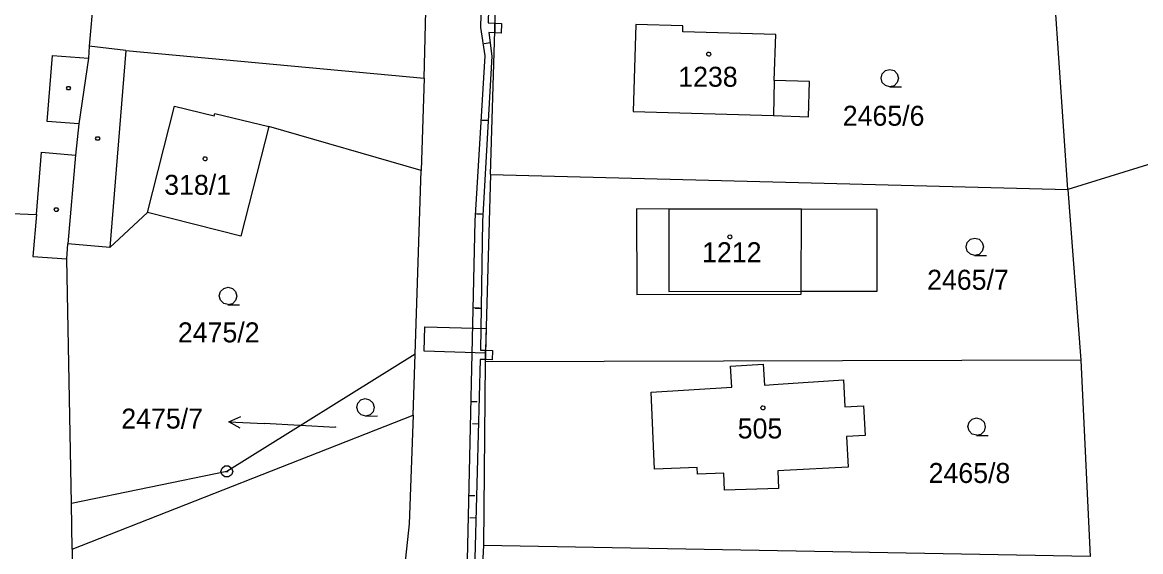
# Model space of a CAD drawing. Extents: x -760611 to -758411, y -1176479 to -1174807.
# Drawn here: x -759156.8 to -759061.6, y -1175074.4 to -1175029.4 of the extents above; entities that cross this region are included whole.
import ezdxf

# ---------------------------------------------------------------- set-up
doc = ezdxf.new("R2010")
doc.units = 0
for name, color, linetype in [('1', 7, 'Continuous'), ('12', 7, 'Continuous'), ('13', 7, 'Continuous'), ('2', 7, 'Continuous'), ('3', 7, 'Continuous'), ('4', 7, 'Continuous'), ('5', 7, 'Continuous'), ('7', 7, 'Continuous'), ('8', 7, 'Continuous')]:
    doc.layers.add(name, color=color, linetype=linetype)

msp = doc.modelspace()

# ---------------------------------------------------------------- linework, layer by layer
at = {"layer": '1'}
for p, q in [((-759122.62, -1175034.09), (-759121.67, -1174994.74)), ((-759149.99, -1175018.59), (-759151.16, -1175031.39)), ((-759116.98, -1175042.31), (-759116.51, -1175026.13)), ((-759067.85, -1175043.58), (-759068.96, -1175027.38)), ((-759104.61, -1175029.53), (-759104.84, -1175036.94)), ((-759100.62, -1175029.65), (-759104.61, -1175029.53)), ((-759100.63, -1175030.15), (-759100.62, -1175029.65)), ((-759092.71, -1175030.39), (-759100.63, -1175030.15)), ((-759092.83, -1175034.29), (-759092.71, -1175030.39)), ((-759025.28, -1175030.41), (-759067.85, -1175043.58)), ((-759151.16, -1175031.39), (-759151.2, -1175032.41)), ((-759148.04, -1175031.75), (-759151.16, -1175031.39)), ((-759151.2, -1175032.41), (-759152.02, -1175037.99)), ((-759148.04, -1175031.75), (-759122.62, -1175034.09)), ((-759122.62, -1175034.09), (-759122.89, -1175041.97)), ((-759089.83, -1175034.38), (-759092.83, -1175034.29)), ((-759089.92, -1175037.38), (-759089.83, -1175034.38)), ((-759104.84, -1175036.94), (-759092.91, -1175037.29)), ((-759152.02, -1175037.99), (-759152.32, -1175040.65)), ((-759092.91, -1175037.29), (-759089.92, -1175037.38)), ((-759135.85, -1175038.22), (-759138.23, -1175047.56)), ((-759122.89, -1175041.97), (-759135.85, -1175038.22)), ((-759152.32, -1175040.65), (-759152.96, -1175048.19)), ((-759123.41, -1175057.6), (-759122.89, -1175041.97)), ((-759116.98, -1175042.31), (-759117.43, -1175058.24)), ((-759116.98, -1175042.31), (-759067.85, -1175043.58)), ((-759067.85, -1175043.58), (-759066.75, -1175058.1)), ((-759158.43, -1175045.59), (-759155.64, -1175045.71)), ((-759155.64, -1175045.71), (-759155.93, -1175049.29)), ((-759146.17, -1175045.54), (-759149.39, -1175048.52)), ((-759138.23, -1175047.56), (-759146.17, -1175045.54)), ((-759101.8, -1175045.24), (-759104.56, -1175045.23)), ((-759104.56, -1175045.23), (-759104.54, -1175052.51)), ((-759090.51, -1175045.26), (-759101.8, -1175045.24)), ((-759084.08, -1175045.27), (-759090.51, -1175045.26)), ((-759084.08, -1175052.24), (-759084.08, -1175045.27)), ((-759153.04, -1175049.47), (-759152.96, -1175048.19)), ((-759149.39, -1175048.52), (-759152.96, -1175048.19)), ((-759155.93, -1175049.29), (-759153.04, -1175049.47)), ((-759152.66, -1175070.32), (-759153.04, -1175049.47)), ((-759090.53, -1175052.49), (-759090.53, -1175052.24)), ((-759090.53, -1175052.24), (-759084.08, -1175052.24)), ((-759104.54, -1175052.51), (-759090.53, -1175052.49)), ((-759123.41, -1175057.6), (-759139.43, -1175067.59)), ((-759123.58, -1175062.8), (-759123.41, -1175057.6)), ((-759066.75, -1175058.1), (-759117.43, -1175058.24)), ((-759066.75, -1175058.1), (-759065.95, -1175074.83)), ((-759117.43, -1175058.24), (-759117.58, -1175073.88)), ((-759096.56, -1175058.61), (-759093.77, -1175058.44)), ((-759096.45, -1175060.41), (-759096.56, -1175058.61)), ((-759093.77, -1175058.44), (-759093.66, -1175060.23)), ((-759092.51, -1175060.16), (-759086.95, -1175059.79)), ((-759086.95, -1175059.79), (-759086.82, -1175062.08)), ((-759103.32, -1175060.84), (-759096.45, -1175060.41)), ((-759103.03, -1175067.39), (-759103.32, -1175060.84)), ((-759093.66, -1175060.23), (-759092.51, -1175060.16)), ((-759152.59, -1175074.2), (-759123.58, -1175062.8)), ((-759123.58, -1175062.8), (-759123.9, -1175072.03)), ((-759086.82, -1175062.08), (-759085.24, -1175061.99)), ((-759085.24, -1175061.99), (-759085.11, -1175064.52)), ((-759085.11, -1175064.52), (-759086.68, -1175064.59)), ((-759086.68, -1175064.59), (-759086.55, -1175067.22)), ((-759139.43, -1175067.59), (-759152.66, -1175070.32)), ((-759099.4, -1175067.24), (-759103.03, -1175067.39)), ((-759099.38, -1175067.81), (-759099.4, -1175067.24)), ((-759092.03, -1175067.51), (-759092.52, -1175067.53)), ((-759092.52, -1175067.53), (-759092.46, -1175069.04)), ((-759086.55, -1175067.22), (-759092.03, -1175067.51)), ((-759097.14, -1175067.72), (-759099.38, -1175067.81)), ((-759097.08, -1175069.18), (-759097.14, -1175067.72)), ((-759092.46, -1175069.04), (-759097.08, -1175069.18)), ((-759152.59, -1175074.2), (-759152.66, -1175070.32)), ((-759123.9, -1175072.03), (-759125.97, -1175090.74)), ((-759152.59, -1175074.2), (-759152.74, -1175108.44)), ((-759117.58, -1175073.88), (-759118.32, -1175086.48)), ((-759065.95, -1175074.83), (-759117.58, -1175073.88))]:
    msp.add_line(p, q, dxfattribs=at)
at = {"layer": '12'}
for p, q in [((-759104.61, -1175029.53), (-759104.84, -1175036.94)), ((-759100.62, -1175029.65), (-759104.61, -1175029.53)), ((-759100.63, -1175030.15), (-759100.62, -1175029.65)), ((-759092.71, -1175030.39), (-759100.63, -1175030.15)), ((-759092.83, -1175034.29), (-759092.71, -1175030.39)), ((-759092.83, -1175034.29), (-759092.91, -1175037.29)), ((-759146.17, -1175045.54), (-759143.89, -1175036.48)), ((-759143.89, -1175036.48), (-759140.5, -1175037.3)), ((-759140.5, -1175037.3), (-759140.44, -1175037.11)), ((-759140.44, -1175037.11), (-759135.85, -1175038.22)), ((-759104.84, -1175036.94), (-759092.91, -1175037.29)), ((-759135.85, -1175038.22), (-759138.23, -1175047.56)), ((-759138.23, -1175047.56), (-759146.17, -1175045.54)), ((-759101.8, -1175045.24), (-759101.81, -1175052.26)), ((-759090.51, -1175045.26), (-759101.8, -1175045.24)), ((-759090.53, -1175052.24), (-759090.51, -1175045.26)), ((-759101.81, -1175052.26), (-759090.53, -1175052.24)), ((-759096.56, -1175058.61), (-759093.77, -1175058.44)), ((-759096.45, -1175060.41), (-759096.56, -1175058.61)), ((-759093.77, -1175058.44), (-759093.66, -1175060.23)), ((-759092.51, -1175060.16), (-759086.95, -1175059.79)), ((-759086.95, -1175059.79), (-759086.82, -1175062.08)), ((-759103.32, -1175060.84), (-759096.45, -1175060.41)), ((-759103.03, -1175067.39), (-759103.32, -1175060.84)), ((-759093.66, -1175060.23), (-759092.51, -1175060.16)), ((-759086.82, -1175062.08), (-759085.24, -1175061.99)), ((-759085.24, -1175061.99), (-759085.11, -1175064.52)), ((-759085.11, -1175064.52), (-759086.68, -1175064.59)), ((-759086.68, -1175064.59), (-759086.55, -1175067.22)), ((-759099.4, -1175067.24), (-759103.03, -1175067.39)), ((-759099.38, -1175067.81), (-759099.4, -1175067.24)), ((-759092.03, -1175067.51), (-759092.52, -1175067.53)), ((-759092.52, -1175067.53), (-759092.46, -1175069.04)), ((-759086.55, -1175067.22), (-759092.03, -1175067.51)), ((-759097.14, -1175067.72), (-759099.38, -1175067.81)), ((-759097.08, -1175069.18), (-759097.14, -1175067.72)), ((-759092.46, -1175069.04), (-759097.08, -1175069.18))]:
    msp.add_line(p, q, dxfattribs=at)
at = {"layer": '13'}
for p, q in [((-759117.02, -1175031.104), (-759117.516, -1175031.17)), ((-759117.771, -1175037.643), (-759117.272, -1175037.672)), ((-759117.187, -1175037.731), (-759117.686, -1175037.702)), ((-759118.243, -1175045.629), (-759117.744, -1175045.658)), ((-759117.648, -1175045.718), (-759118.147, -1175045.689)), ((-759118.449, -1175053.626), (-759117.949, -1175053.637)), ((-759117.795, -1175053.716), (-759118.295, -1175053.708)), ((-759122.63, -1175057.35), (-759122.57, -1175055.26)), ((-759122.57, -1175055.26), (-759117.35, -1175055.41)), ((-759117.35, -1175055.41), (-759117.41, -1175057.5)), ((-759117.41, -1175057.5), (-759122.63, -1175057.35)), ((-759118.631, -1175061.624), (-759118.132, -1175061.635)), ((-759118.02, -1175063.548), (-759118.52, -1175063.534)), ((-759118.814, -1175069.621), (-759118.314, -1175069.633)), ((-759118.238, -1175071.545), (-759118.738, -1175071.531))]:
    msp.add_line(p, q, dxfattribs=at)
for points in [[(-759117.8, -1175029.8), (-759117.31, -1175010.26), (-759116.14, -1174991.67), (-759120.15, -1174990.8), (-759120.24, -1174991.77), (-759121.26, -1174991.7), (-759121.06, -1174989.59)], [(-759116.72, -1175010.71), (-759117.19, -1175029.4), (-759116.61, -1175029.43), (-759116.63, -1175030.23), (-759117.14, -1175030.2), (-759116.87, -1175032.24)], [(-759118.94, -1175075.12), (-759118.28, -1175046.25), (-759117.45, -1175032.21), (-759117.8, -1175029.8)], [(-759116.87, -1175032.24), (-759117.68, -1175046.27), (-759117.85, -1175057.25), (-759117.4, -1175057.26), (-759117.42, -1175058.06), (-759117.87, -1175058.05)], [(-759117.87, -1175058.05), (-759118.39, -1175077.12), (-759117.86, -1175077.16), (-759117.9, -1175077.96), (-759118.45, -1175077.92), (-759119.04, -1175094.45), (-759118.58, -1175094.46), (-759118.6, -1175095.26)]]:
    msp.add_lwpolyline(points, dxfattribs=at)
for points in [[(-759116.05, -1175029.46), (-759116.09, -1175030.26), (-759116.63, -1175030.23), (-759116.61, -1175029.43)], [(-759116.82, -1175057.27), (-759116.84, -1175058.07), (-759117.42, -1175058.06), (-759117.4, -1175057.26)]]:
    msp.add_lwpolyline(points, close=True, dxfattribs=at)
at = {"layer": '3'}
for points in [[(-759082.99, -1175034.83), (-759083.37, -1175034.73), (-759083.64, -1175034.46), (-759083.74, -1175034.09), (-759083.64, -1175033.72), (-759083.37, -1175033.45), (-759083, -1175033.35), (-759082.63, -1175033.45), (-759082.36, -1175033.72), (-759082.26, -1175034.1), (-759082.36, -1175034.48), (-759082.63, -1175034.75), (-759083.01, -1175034.85), (-759082.01, -1175034.85)], [(-759075.76, -1175049.19), (-759076.14, -1175049.09), (-759076.41, -1175048.82), (-759076.51, -1175048.45), (-759076.41, -1175048.08), (-759076.14, -1175047.81), (-759075.77, -1175047.71), (-759075.4, -1175047.81), (-759075.13, -1175048.08), (-759075.03, -1175048.46), (-759075.13, -1175048.84), (-759075.4, -1175049.11), (-759075.78, -1175049.21), (-759074.78, -1175049.21)], [(-759139.32, -1175053.38), (-759139.7, -1175053.28), (-759139.97, -1175053.01), (-759140.07, -1175052.64), (-759139.97, -1175052.27), (-759139.7, -1175052), (-759139.33, -1175051.9), (-759138.96, -1175052), (-759138.69, -1175052.27), (-759138.59, -1175052.65), (-759138.69, -1175053.03), (-759138.96, -1175053.3), (-759139.34, -1175053.4), (-759138.34, -1175053.4)], [(-759127.6, -1175062.86), (-759127.983, -1175062.772), (-759128.261, -1175062.51), (-759128.373, -1175062.144), (-759128.284, -1175061.771), (-759128.023, -1175061.492), (-759127.656, -1175061.381), (-759127.283, -1175061.47), (-759127.005, -1175061.731), (-759126.893, -1175062.108), (-759126.981, -1175062.491), (-759127.243, -1175062.769), (-759127.619, -1175062.881), (-759126.62, -1175062.85)], [(-759075.6, -1175064.5), (-759075.98, -1175064.4), (-759076.25, -1175064.13), (-759076.35, -1175063.76), (-759076.25, -1175063.39), (-759075.98, -1175063.12), (-759075.61, -1175063.02), (-759075.24, -1175063.12), (-759074.97, -1175063.39), (-759074.87, -1175063.77), (-759074.97, -1175064.15), (-759075.24, -1175064.42), (-759075.62, -1175064.52), (-759074.62, -1175064.52)]]:
    msp.add_lwpolyline(points, dxfattribs=at)
at = {"layer": '4'}
for p, q in [((-759154.71, -1175037.78), (-759154.26, -1175032.17)), ((-759154.26, -1175032.17), (-759151.2, -1175032.41)), ((-759148.04, -1175031.75), (-759149.39, -1175048.52)), ((-759092.83, -1175034.29), (-759092.91, -1175037.29)), ((-759146.17, -1175045.54), (-759143.89, -1175036.48)), ((-759143.89, -1175036.48), (-759140.5, -1175037.3)), ((-759140.5, -1175037.3), (-759140.44, -1175037.11)), ((-759140.44, -1175037.11), (-759135.85, -1175038.22)), ((-759152.02, -1175037.99), (-759154.71, -1175037.78)), ((-759155.64, -1175045.71), (-759155.21, -1175040.41)), ((-759155.21, -1175040.41), (-759152.32, -1175040.65)), ((-759101.8, -1175045.24), (-759101.81, -1175052.26)), ((-759090.53, -1175052.24), (-759090.51, -1175045.26)), ((-759101.81, -1175052.26), (-759090.53, -1175052.24))]:
    msp.add_line(p, q, dxfattribs=at)
at = {"layer": '5'}
for points in [[(-759098.41, -1175031.89), (-759098.31, -1175031.91), (-759098.26, -1175032), (-759098.24, -1175032.06), (-759098.26, -1175032.15), (-759098.34, -1175032.22), (-759098.41, -1175032.23), (-759098.5, -1175032.2), (-759098.56, -1175032.14), (-759098.58, -1175032.06), (-759098.56, -1175031.97), (-759098.48, -1175031.9)], [(-759152.82, -1175034.8), (-759152.73, -1175034.95), (-759152.82, -1175035.1), (-759153, -1175035.1), (-759153.09, -1175034.95), (-759153, -1175034.8)], [(-759150.34, -1175039.09), (-759150.25, -1175039.24), (-759150.34, -1175039.39), (-759150.52, -1175039.39), (-759150.61, -1175039.24), (-759150.52, -1175039.09)], [(-759141.28, -1175040.8), (-759141.18, -1175040.82), (-759141.13, -1175040.91), (-759141.11, -1175040.97), (-759141.13, -1175041.06), (-759141.21, -1175041.13), (-759141.28, -1175041.14), (-759141.37, -1175041.11), (-759141.43, -1175041.05), (-759141.45, -1175040.97), (-759141.43, -1175040.88), (-759141.35, -1175040.81)], [(-759153.86, -1175045.14), (-759153.77, -1175045.29), (-759153.86, -1175045.44), (-759154.04, -1175045.44), (-759154.13, -1175045.29), (-759154.04, -1175045.14)], [(-759096.62, -1175047.45), (-759096.52, -1175047.47), (-759096.47, -1175047.56), (-759096.45, -1175047.62), (-759096.47, -1175047.71), (-759096.55, -1175047.78), (-759096.62, -1175047.79), (-759096.71, -1175047.76), (-759096.77, -1175047.7), (-759096.79, -1175047.62), (-759096.77, -1175047.53), (-759096.69, -1175047.46)], [(-759093.8, -1175061.99), (-759093.7, -1175062.01), (-759093.65, -1175062.1), (-759093.63, -1175062.16), (-759093.65, -1175062.25), (-759093.73, -1175062.32), (-759093.8, -1175062.33), (-759093.89, -1175062.3), (-759093.95, -1175062.24), (-759093.97, -1175062.16), (-759093.95, -1175062.07), (-759093.87, -1175062)]]:
    msp.add_lwpolyline(points, close=True, dxfattribs=at)
at = {"layer": '7'}
for p in [(-759139.255, -1175063.346), (-759130.18, -1175063.84)]:
    msp.add_line(p, (-759136.26, -1175063.51), dxfattribs=at)
msp.add_lwpolyline([(-759138.284, -1175063.9), (-759139.255, -1175063.346), (-759138.23, -1175062.901)], dxfattribs=at)
at = {"layer": '8'}
msp.add_line((-759139.55, -1175067.59), (-759139.31, -1175067.59), dxfattribs=at)
msp.add_lwpolyline([(-759139.28, -1175067.11), (-759139.03, -1175067.29), (-759138.93, -1175067.58), (-759139.03, -1175067.87), (-759139.28, -1175068.05), (-759139.59, -1175068.05), (-759139.84, -1175067.87), (-759139.94, -1175067.58), (-759139.84, -1175067.29), (-759139.59, -1175067.11)], close=True, dxfattribs=at)

# ---------------------------------------------------------------- texts
at = {"layer": '2'}
for s, height, p in [('1238', 1.7, (-759101.006, -1175034.83)), ('2465/6', 1.7, (-759087.003, -1175038.15)), ('318/1', 1.7, (-759144.761, -1175044.03)), ('1212', 1.7, (-759098.975, -1175049.77)), ('2465/7', 1.7, (-759079.823, -1175052.11)), ('2475/2', 1.7, (-759143.596, -1175056.59)), ('2475/7', 0.1, (-759130.425, -1175063.84)), ('505', 1.7, (-759095.945, -1175064.77)), ('2465/8', 1.7, (-759079.693, -1175068.56))]:
    msp.add_text(s, height=height, dxfattribs=at).set_placement(p)
at = {"layer": '7'}
msp.add_text('2475/7', height=1.7, dxfattribs=at).set_placement((-759148.413, -1175063.93))

doc.saveas('drawing.dxf')
